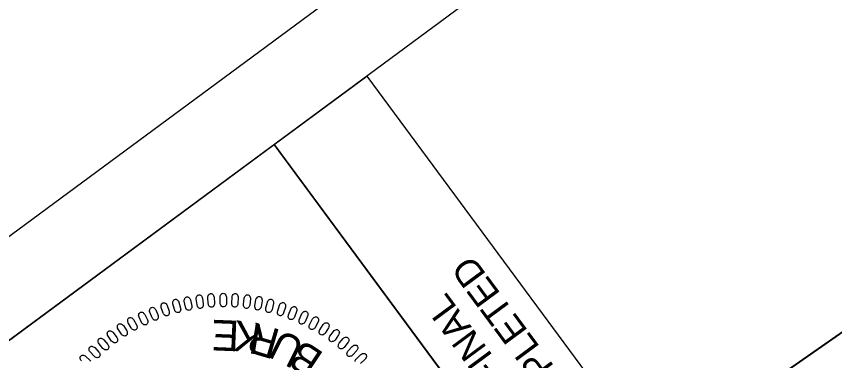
# Model space of a CAD drawing. Extents: x 474314 to 476195, y 501901 to 503905.
# Drawn here: x 474410.1 to 474577, y 503299.5 to 503369.8 of the extents above; entities that cross this region are included whole.
import ezdxf

# ---------------------------------------------------------------- set-up
doc = ezdxf.new("R2010")
doc.units = 0
for name, color, linetype in [('Matchline', 7, 'Continuous'), ('Sheet Clip Boundary CELL', 7, 'Continuous'), ('Sheet PE Seal Cell', 7, 'Continuous'), ('Sheet Plan CELL', 7, 'Continuous'), ('Sheet Plot Border Outside CELL', 7, 'Continuous'), ('Sheet Sticker Exception Certification CELL', 7, 'Continuous')]:
    doc.layers.add(name, color=color, linetype=linetype)

msp = doc.modelspace()

# ---------------------------------------------------------------- linework, layer by layer
at = {"layer": 'Matchline'}
msp.add_line((475026.19, 503617.59), (474539.84, 503278.31), dxfattribs=at)
at = {"layer": 'Sheet Clip Boundary CELL'}
msp.add_lwpolyline([(474600.43, 503196.68), (474460.82, 503093.56), (475070.85, 502267.56), (475070.85, 502267.56), (475070.85, 502267.56), (475070.85, 502267.56), (475070.85, 502267.56), (475070.85, 502267.56), (475422.16, 502337.99), (475422.16, 502337.99), (476046.45, 502713.99), (475412.07, 503572.99), (475380.25, 503549.49), (475256.12, 503717.56), (475223.58, 503693.53), (475026.19, 503617.59), (474539.96, 503278.51)], close=True, dxfattribs=at)
at = {"layer": 'Sheet PE Seal Cell'}
for points in [[(474446.97, 503310.9), (474446.81, 503312.12), (474446.82, 503312.34), (474446.85, 503312.48), (474446.94, 503312.67), (474447.02, 503312.79), (474447.12, 503312.88), (474447.22, 503312.93), (474447.33, 503312.97), (474447.44, 503312.96), (474447.56, 503312.95), (474447.67, 503312.91), (474447.79, 503312.82), (474447.86, 503312.75), (474447.95, 503312.61), (474448.03, 503312.44), (474448.07, 503312.29), (474448.25, 503311.04), (474448.25, 503310.87), (474448.22, 503310.72), (474448.16, 503310.56), (474448.06, 503310.4), (474447.98, 503310.31), (474447.83, 503310.23), (474447.68, 503310.19), (474447.53, 503310.21), (474447.42, 503310.25), (474447.28, 503310.33), (474447.14, 503310.48), (474447.05, 503310.65), (474447, 503310.77)], [(474449.26, 503311.18), (474449.18, 503312.4), (474449.2, 503312.63), (474449.24, 503312.77), (474449.34, 503312.95), (474449.43, 503313.06), (474449.54, 503313.15), (474449.64, 503313.2), (474449.75, 503313.22), (474449.86, 503313.21), (474449.98, 503313.19), (474450.09, 503313.14), (474450.2, 503313.05), (474450.27, 503312.97), (474450.35, 503312.83), (474450.42, 503312.65), (474450.45, 503312.49), (474450.55, 503311.24), (474450.54, 503311.07), (474450.5, 503310.93), (474450.42, 503310.76), (474450.32, 503310.61), (474450.23, 503310.53), (474450.08, 503310.46), (474449.93, 503310.43), (474449.78, 503310.46), (474449.67, 503310.5), (474449.54, 503310.59), (474449.41, 503310.75), (474449.33, 503310.92), (474449.29, 503311.05)], [(474451.69, 503311.28), (474451.68, 503312.51), (474451.72, 503312.73), (474451.77, 503312.87), (474451.88, 503313.04), (474451.98, 503313.15), (474452.09, 503313.23), (474452.19, 503313.27), (474452.31, 503313.29), (474452.42, 503313.27), (474452.54, 503313.24), (474452.64, 503313.19), (474452.75, 503313.09), (474452.81, 503313.01), (474452.88, 503312.86), (474452.94, 503312.68), (474452.96, 503312.52), (474452.98, 503311.26), (474452.96, 503311.09), (474452.91, 503310.95), (474452.83, 503310.79), (474452.72, 503310.65), (474452.62, 503310.57), (474452.46, 503310.51), (474452.31, 503310.49), (474452.16, 503310.53), (474452.06, 503310.58), (474451.93, 503310.68), (474451.81, 503310.84), (474451.74, 503311.02), (474451.71, 503311.15)], [(474454.04, 503311.27), (474454.11, 503312.49), (474454.16, 503312.71), (474454.22, 503312.85), (474454.34, 503313.01), (474454.44, 503313.12), (474454.56, 503313.19), (474454.67, 503313.22), (474454.78, 503313.24), (474454.89, 503313.21), (474455.01, 503313.17), (474455.11, 503313.11), (474455.21, 503313), (474455.26, 503312.92), (474455.32, 503312.77), (474455.37, 503312.58), (474455.38, 503312.42), (474455.32, 503311.17), (474455.29, 503311), (474455.24, 503310.86), (474455.14, 503310.71), (474455.02, 503310.58), (474454.92, 503310.5), (474454.76, 503310.45), (474454.61, 503310.44), (474454.46, 503310.49), (474454.36, 503310.54), (474454.24, 503310.65), (474454.13, 503310.83), (474454.07, 503311.01), (474454.05, 503311.14)], [(474456.44, 503311.06), (474456.59, 503312.28), (474456.65, 503312.49), (474456.72, 503312.63), (474456.85, 503312.78), (474456.96, 503312.88), (474457.08, 503312.95), (474457.19, 503312.97), (474457.3, 503312.98), (474457.41, 503312.95), (474457.53, 503312.9), (474457.63, 503312.83), (474457.72, 503312.72), (474457.77, 503312.63), (474457.82, 503312.48), (474457.86, 503312.29), (474457.86, 503312.13), (474457.72, 503310.88), (474457.68, 503310.72), (474457.61, 503310.58), (474457.51, 503310.43), (474457.38, 503310.31), (474457.27, 503310.24), (474457.11, 503310.2), (474456.96, 503310.2), (474456.82, 503310.26), (474456.72, 503310.32), (474456.6, 503310.43), (474456.5, 503310.61), (474456.46, 503310.8), (474456.44, 503310.93)], [(474440.06, 503309.24), (474439.67, 503310.41), (474439.64, 503310.63), (474439.64, 503310.77), (474439.7, 503310.97), (474439.75, 503311.11), (474439.84, 503311.22), (474439.92, 503311.29), (474440.02, 503311.34), (474440.13, 503311.36), (474440.26, 503311.37), (474440.38, 503311.34), (474440.51, 503311.28), (474440.59, 503311.23), (474440.7, 503311.11), (474440.81, 503310.95), (474440.88, 503310.81), (474441.29, 503309.62), (474441.32, 503309.45), (474441.32, 503309.31), (474441.29, 503309.13), (474441.23, 503308.96), (474441.16, 503308.85), (474441.03, 503308.74), (474440.89, 503308.68), (474440.74, 503308.67), (474440.62, 503308.68), (474440.47, 503308.74), (474440.3, 503308.86), (474440.18, 503309.01), (474440.12, 503309.12)], [(474442.37, 503309.95), (474442.05, 503311.14), (474442.03, 503311.36), (474442.05, 503311.51), (474442.11, 503311.7), (474442.18, 503311.83), (474442.27, 503311.94), (474442.36, 503312), (474442.46, 503312.05), (474442.58, 503312.06), (474442.7, 503312.06), (474442.82, 503312.03), (474442.94, 503311.96), (474443.02, 503311.9), (474443.12, 503311.77), (474443.23, 503311.61), (474443.29, 503311.46), (474443.62, 503310.25), (474443.64, 503310.08), (474443.63, 503309.93), (474443.59, 503309.76), (474443.51, 503309.59), (474443.44, 503309.49), (474443.3, 503309.39), (474443.17, 503309.34), (474443.01, 503309.34), (474442.9, 503309.36), (474442.75, 503309.42), (474442.59, 503309.56), (474442.48, 503309.71), (474442.42, 503309.83)], [(474444.62, 503310.47), (474444.38, 503311.67), (474444.38, 503311.89), (474444.4, 503312.04), (474444.48, 503312.23), (474444.55, 503312.35), (474444.64, 503312.45), (474444.74, 503312.51), (474444.84, 503312.56), (474444.96, 503312.56), (474445.08, 503312.55), (474445.2, 503312.51), (474445.32, 503312.44), (474445.39, 503312.37), (474445.49, 503312.24), (474445.58, 503312.07), (474445.63, 503311.92), (474445.89, 503310.69), (474445.9, 503310.52), (474445.88, 503310.37), (474445.82, 503310.2), (474445.74, 503310.04), (474445.66, 503309.94), (474445.52, 503309.85), (474445.38, 503309.8), (474445.22, 503309.81), (474445.11, 503309.84), (474444.96, 503309.92), (474444.81, 503310.06), (474444.71, 503310.22), (474444.66, 503310.34)], [(474458.77, 503310.77), (474458.99, 503311.98), (474459.06, 503312.19), (474459.14, 503312.32), (474459.28, 503312.46), (474459.4, 503312.55), (474459.52, 503312.61), (474459.63, 503312.63), (474459.74, 503312.63), (474459.85, 503312.59), (474459.96, 503312.54), (474460.05, 503312.46), (474460.14, 503312.35), (474460.18, 503312.26), (474460.22, 503312.1), (474460.25, 503311.91), (474460.24, 503311.75), (474460.02, 503310.51), (474459.97, 503310.35), (474459.9, 503310.22), (474459.79, 503310.08), (474459.65, 503309.96), (474459.54, 503309.9), (474459.38, 503309.87), (474459.22, 503309.88), (474459.08, 503309.94), (474458.99, 503310.01), (474458.88, 503310.13), (474458.8, 503310.32), (474458.76, 503310.51), (474458.76, 503310.64)], [(474461.02, 503310.29), (474461.32, 503311.48), (474461.41, 503311.68), (474461.49, 503311.8), (474461.64, 503311.94), (474461.76, 503312.03), (474461.89, 503312.08), (474462, 503312.09), (474462.12, 503312.08), (474462.22, 503312.03), (474462.33, 503311.98), (474462.42, 503311.89), (474462.5, 503311.77), (474462.53, 503311.68), (474462.56, 503311.52), (474462.58, 503311.33), (474462.56, 503311.17), (474462.27, 503309.95), (474462.2, 503309.79), (474462.12, 503309.66), (474462, 503309.53), (474461.86, 503309.42), (474461.74, 503309.37), (474461.58, 503309.35), (474461.43, 503309.37), (474461.29, 503309.44), (474461.2, 503309.51), (474461.1, 503309.64), (474461.03, 503309.83), (474461.01, 503310.03), (474461.01, 503310.16)], [(474463.42, 503309.68), (474463.79, 503310.85), (474463.89, 503311.05), (474463.98, 503311.17), (474464.14, 503311.3), (474464.26, 503311.37), (474464.4, 503311.41), (474464.51, 503311.42), (474464.62, 503311.41), (474464.72, 503311.35), (474464.83, 503311.29), (474464.91, 503311.2), (474464.98, 503311.07), (474465.01, 503310.98), (474465.03, 503310.82), (474465.03, 503310.63), (474465.01, 503310.47), (474464.63, 503309.27), (474464.56, 503309.11), (474464.48, 503308.99), (474464.34, 503308.87), (474464.19, 503308.77), (474464.08, 503308.72), (474463.91, 503308.71), (474463.76, 503308.74), (474463.63, 503308.82), (474463.54, 503308.9), (474463.45, 503309.03), (474463.39, 503309.23), (474463.38, 503309.42), (474463.39, 503309.56)], [(474435.68, 503307.32), (474435.15, 503308.42), (474435.09, 503308.64), (474435.07, 503308.79), (474435.1, 503308.99), (474435.14, 503309.13), (474435.21, 503309.25), (474435.29, 503309.33), (474435.38, 503309.4), (474435.49, 503309.43), (474435.61, 503309.45), (474435.73, 503309.44), (474435.87, 503309.4), (474435.96, 503309.35), (474436.08, 503309.25), (474436.21, 503309.11), (474436.3, 503308.98), (474436.85, 503307.85), (474436.91, 503307.68), (474436.93, 503307.54), (474436.91, 503307.36), (474436.87, 503307.18), (474436.82, 503307.07), (474436.7, 503306.95), (474436.58, 503306.86), (474436.43, 503306.83), (474436.31, 503306.83), (474436.15, 503306.87), (474435.97, 503306.97), (474435.83, 503307.1), (474435.75, 503307.21)], [(474437.82, 503308.3), (474437.36, 503309.43), (474437.31, 503309.65), (474437.3, 503309.8), (474437.34, 503310), (474437.39, 503310.14), (474437.47, 503310.25), (474437.55, 503310.33), (474437.65, 503310.39), (474437.76, 503310.41), (474437.88, 503310.43), (474438, 503310.41), (474438.13, 503310.36), (474438.22, 503310.31), (474438.34, 503310.2), (474438.46, 503310.05), (474438.54, 503309.91), (474439.02, 503308.75), (474439.06, 503308.59), (474439.07, 503308.44), (474439.05, 503308.26), (474439, 503308.09), (474438.94, 503307.98), (474438.81, 503307.86), (474438.68, 503307.79), (474438.53, 503307.77), (474438.41, 503307.77), (474438.26, 503307.82), (474438.08, 503307.93), (474437.95, 503308.07), (474437.88, 503308.18)], [(474465.64, 503308.91), (474466.08, 503310.05), (474466.2, 503310.24), (474466.3, 503310.36), (474466.46, 503310.47), (474466.59, 503310.54), (474466.73, 503310.57), (474466.84, 503310.57), (474466.95, 503310.55), (474467.05, 503310.49), (474467.15, 503310.42), (474467.22, 503310.33), (474467.29, 503310.2), (474467.31, 503310.1), (474467.32, 503309.94), (474467.31, 503309.75), (474467.28, 503309.59), (474466.83, 503308.42), (474466.75, 503308.27), (474466.65, 503308.15), (474466.51, 503308.04), (474466.36, 503307.95), (474466.24, 503307.91), (474466.07, 503307.91), (474465.92, 503307.94), (474465.8, 503308.04), (474465.72, 503308.12), (474465.64, 503308.26), (474465.59, 503308.46), (474465.59, 503308.65), (474465.61, 503308.78)], [(474467.85, 503308.03), (474468.36, 503309.15), (474468.49, 503309.33), (474468.6, 503309.43), (474468.77, 503309.54), (474468.9, 503309.6), (474469.04, 503309.63), (474469.15, 503309.62), (474469.26, 503309.59), (474469.35, 503309.52), (474469.45, 503309.45), (474469.52, 503309.35), (474469.57, 503309.21), (474469.59, 503309.12), (474469.59, 503308.95), (474469.57, 503308.76), (474469.52, 503308.61), (474469, 503307.47), (474468.91, 503307.32), (474468.81, 503307.21), (474468.67, 503307.11), (474468.51, 503307.03), (474468.38, 503306.99), (474468.22, 503307.01), (474468.07, 503307.05), (474467.95, 503307.15), (474467.88, 503307.24), (474467.8, 503307.38), (474467.77, 503307.59), (474467.78, 503307.78), (474467.81, 503307.91)], [(474433.52, 503306.22), (474432.93, 503307.29), (474432.85, 503307.5), (474432.83, 503307.65), (474432.84, 503307.85), (474432.87, 503307.99), (474432.93, 503308.12), (474433.01, 503308.2), (474433.09, 503308.27), (474433.2, 503308.31), (474433.32, 503308.34), (474433.44, 503308.34), (474433.58, 503308.31), (474433.67, 503308.27), (474433.8, 503308.17), (474433.94, 503308.04), (474434.04, 503307.91), (474434.66, 503306.82), (474434.72, 503306.66), (474434.75, 503306.52), (474434.75, 503306.33), (474434.72, 503306.16), (474434.68, 503306.04), (474434.57, 503305.91), (474434.45, 503305.82), (474434.3, 503305.78), (474434.18, 503305.78), (474434.02, 503305.8), (474433.84, 503305.89), (474433.69, 503306.01), (474433.6, 503306.11)], [(474469.95, 503306.97), (474470.54, 503308.05), (474470.67, 503308.23), (474470.79, 503308.33), (474470.97, 503308.42), (474471.1, 503308.47), (474471.24, 503308.49), (474471.35, 503308.47), (474471.46, 503308.44), (474471.55, 503308.37), (474471.64, 503308.28), (474471.7, 503308.18), (474471.75, 503308.04), (474471.76, 503307.95), (474471.75, 503307.78), (474471.72, 503307.6), (474471.66, 503307.44), (474471.07, 503306.34), (474470.97, 503306.2), (474470.86, 503306.1), (474470.71, 503306), (474470.54, 503305.93), (474470.42, 503305.9), (474470.25, 503305.93), (474470.11, 503305.98), (474470, 503306.09), (474469.93, 503306.18), (474469.87, 503306.33), (474469.84, 503306.53), (474469.87, 503306.72), (474469.91, 503306.85)], [(474431.54, 503304.96), (474430.88, 503305.99), (474430.79, 503306.2), (474430.76, 503306.34), (474430.76, 503306.55), (474430.78, 503306.69), (474430.83, 503306.82), (474430.9, 503306.91), (474430.98, 503306.99), (474431.09, 503307.03), (474431.21, 503307.07), (474431.33, 503307.08), (474431.47, 503307.05), (474431.56, 503307.02), (474431.7, 503306.93), (474431.85, 503306.81), (474431.95, 503306.69), (474432.64, 503305.63), (474432.71, 503305.48), (474432.75, 503305.34), (474432.76, 503305.16), (474432.74, 503304.98), (474432.71, 503304.86), (474432.61, 503304.72), (474432.49, 503304.62), (474432.34, 503304.58), (474432.23, 503304.56), (474432.07, 503304.58), (474431.88, 503304.65), (474431.72, 503304.77), (474431.63, 503304.86)], [(474472.03, 503305.86), (474472.68, 503306.9), (474472.83, 503307.07), (474472.94, 503307.16), (474473.13, 503307.24), (474473.27, 503307.28), (474473.41, 503307.29), (474473.52, 503307.27), (474473.62, 503307.23), (474473.71, 503307.15), (474473.79, 503307.06), (474473.85, 503306.96), (474473.89, 503306.82), (474473.89, 503306.72), (474473.87, 503306.55), (474473.83, 503306.37), (474473.76, 503306.22), (474473.1, 503305.15), (474472.99, 503305.02), (474472.88, 503304.93), (474472.72, 503304.84), (474472.55, 503304.78), (474472.43, 503304.76), (474472.26, 503304.8), (474472.12, 503304.86), (474472.02, 503304.97), (474471.96, 503305.07), (474471.9, 503305.22), (474471.89, 503305.43), (474471.93, 503305.62), (474471.97, 503305.74)], [(474429.56, 503303.54), (474428.83, 503304.53), (474428.73, 503304.73), (474428.69, 503304.87), (474428.68, 503305.07), (474428.69, 503305.22), (474428.74, 503305.35), (474428.8, 503305.44), (474428.88, 503305.53), (474428.98, 503305.58), (474429.09, 503305.62), (474429.21, 503305.64), (474429.35, 503305.62), (474429.45, 503305.59), (474429.59, 503305.51), (474429.75, 503305.4), (474429.86, 503305.29), (474430.61, 503304.28), (474430.7, 503304.13), (474430.74, 503303.99), (474430.76, 503303.81), (474430.76, 503303.63), (474430.73, 503303.51), (474430.64, 503303.37), (474430.53, 503303.26), (474430.38, 503303.2), (474430.27, 503303.18), (474430.11, 503303.19), (474429.91, 503303.25), (474429.75, 503303.36), (474429.65, 503303.44)], [(474474.08, 503304.53), (474474.79, 503305.52), (474474.95, 503305.68), (474475.08, 503305.76), (474475.27, 503305.84), (474475.41, 503305.87), (474475.55, 503305.87), (474475.65, 503305.84), (474475.76, 503305.79), (474475.84, 503305.71), (474475.92, 503305.62), (474475.97, 503305.51), (474475.99, 503305.36), (474476, 503305.26), (474475.96, 503305.1), (474475.91, 503304.92), (474475.83, 503304.78), (474475.11, 503303.75), (474474.99, 503303.63), (474474.87, 503303.54), (474474.71, 503303.46), (474474.54, 503303.42), (474474.41, 503303.41), (474474.25, 503303.45), (474474.12, 503303.52), (474474.02, 503303.64), (474473.96, 503303.74), (474473.91, 503303.9), (474473.92, 503304.1), (474473.97, 503304.29), (474474.02, 503304.41)], [(474427.77, 503302.04), (474426.99, 503302.97), (474426.87, 503303.17), (474426.82, 503303.31), (474426.8, 503303.51), (474426.8, 503303.66), (474426.84, 503303.79), (474426.89, 503303.89), (474426.97, 503303.97), (474427.06, 503304.03), (474427.18, 503304.08), (474427.29, 503304.11), (474427.44, 503304.1), (474427.54, 503304.07), (474427.68, 503304), (474427.85, 503303.9), (474427.96, 503303.8), (474428.78, 503302.84), (474428.87, 503302.69), (474428.93, 503302.56), (474428.96, 503302.38), (474428.96, 503302.2), (474428.94, 503302.08), (474428.86, 503301.93), (474428.76, 503301.82), (474428.62, 503301.75), (474428.5, 503301.72), (474428.34, 503301.72), (474428.14, 503301.77), (474427.98, 503301.87), (474427.87, 503301.95)], [(474475.98, 503303.08), (474476.76, 503304.03), (474476.92, 503304.18), (474477.05, 503304.25), (474477.25, 503304.31), (474477.39, 503304.34), (474477.53, 503304.33), (474477.64, 503304.29), (474477.74, 503304.24), (474477.81, 503304.15), (474477.88, 503304.05), (474477.93, 503303.94), (474477.94, 503303.8), (474477.94, 503303.7), (474477.9, 503303.54), (474477.83, 503303.36), (474477.75, 503303.22), (474476.96, 503302.25), (474476.84, 503302.13), (474476.71, 503302.05), (474476.54, 503301.98), (474476.37, 503301.94), (474476.24, 503301.94), (474476.08, 503302), (474475.95, 503302.08), (474475.86, 503302.2), (474475.81, 503302.31), (474475.78, 503302.46), (474475.79, 503302.67), (474475.85, 503302.85), (474475.91, 503302.97)], [(474477.77, 503301.56), (474478.61, 503302.46), (474478.78, 503302.6), (474478.92, 503302.67), (474479.11, 503302.71), (474479.26, 503302.73), (474479.4, 503302.71), (474479.5, 503302.67), (474479.6, 503302.61), (474479.66, 503302.52), (474479.73, 503302.41), (474479.77, 503302.3), (474479.78, 503302.15), (474479.77, 503302.05), (474479.71, 503301.9), (474479.64, 503301.73), (474479.54, 503301.59), (474478.7, 503300.67), (474478.57, 503300.56), (474478.44, 503300.49), (474478.26, 503300.43), (474478.09, 503300.4), (474477.96, 503300.41), (474477.8, 503300.47), (474477.68, 503300.56), (474477.6, 503300.69), (474477.56, 503300.8), (474477.53, 503300.96), (474477.56, 503301.16), (474477.63, 503301.34), (474477.7, 503301.46)], [(474426.02, 503300.43), (474425.17, 503301.32), (474425.05, 503301.51), (474424.99, 503301.64), (474424.95, 503301.84), (474424.95, 503301.99), (474424.97, 503302.13), (474425.02, 503302.23), (474425.09, 503302.32), (474425.18, 503302.38), (474425.29, 503302.44), (474425.41, 503302.47), (474425.55, 503302.47), (474425.65, 503302.45), (474425.8, 503302.39), (474425.97, 503302.3), (474426.1, 503302.2), (474426.97, 503301.3), (474427.07, 503301.16), (474427.13, 503301.03), (474427.18, 503300.85), (474427.19, 503300.67), (474427.18, 503300.55), (474427.11, 503300.4), (474427.01, 503300.28), (474426.88, 503300.21), (474426.77, 503300.17), (474426.6, 503300.15), (474426.4, 503300.19), (474426.23, 503300.28), (474426.12, 503300.35)]]:
    msp.add_lwpolyline(points, close=True, dxfattribs=at)
for points in [[(474423.39, 503299.5), (474423.26, 503299.67), (474423.19, 503299.81), (474423.14, 503300.01), (474423.13, 503300.15), (474423.14, 503300.29), (474423.18, 503300.39), (474423.25, 503300.49), (474423.34, 503300.56), (474423.44, 503300.62), (474423.55, 503300.66), (474423.7, 503300.67), (474423.8, 503300.66), (474423.95, 503300.61), (474424.13, 503300.53), (474424.26, 503300.44), (474425.19, 503299.59), (474425.3, 503299.46)], [(474479.2, 503299.36), (474479.24, 503299.56), (474479.32, 503299.73), (474479.39, 503299.84), (474479.48, 503299.94), (474480.37, 503300.79), (474480.55, 503300.91), (474480.69, 503300.97), (474480.89, 503301.01), (474481.03, 503301.01), (474481.17, 503300.99), (474481.27, 503300.94), (474481.36, 503300.87), (474481.43, 503300.78), (474481.49, 503300.67), (474481.52, 503300.55), (474481.52, 503300.41), (474481.5, 503300.31), (474481.44, 503300.16), (474481.35, 503299.99), (474481.25, 503299.86), (474480.34, 503298.99)]]:
    msp.add_lwpolyline(points, dxfattribs=at)
at = {"layer": 'Sheet Plan CELL'}
for points in [[(474341.97, 503254.51), (475233.1, 502047.86), (476077.73, 502671.64), (475186.62, 503878.27)], [(474431.61, 503196.37), (474372.2, 503276.79), (474462.7, 503343.64), (474522.12, 503263.21)]]:
    msp.add_lwpolyline(points, close=True, dxfattribs=at)
at = {"layer": 'Sheet Plot Border Outside CELL'}
msp.add_lwpolyline([(476194.75, 502551.08), (475194.63, 503905.31), (474313.8, 503254.81), (475313.91, 501900.58)], close=True, dxfattribs=at)
at = {"layer": 'Sheet Sticker Exception Certification CELL'}
for p, q in [((474462.7, 503343.64), (474481.6, 503357.6)), ((474462.7, 503343.64), (474481.6, 503357.6)), ((474481.59, 503357.59), (474600.43, 503196.68)), ((474481.59, 503357.59), (474600.43, 503196.68)), ((474581.52, 503182.72), (474462.69, 503343.63)), ((474581.52, 503182.72), (474462.69, 503343.63))]:
    msp.add_line(p, q, dxfattribs=at)

# ---------------------------------------------------------------- texts
at = {"layer": 'Sheet PE Seal Cell'}
for s, rotation, p in [('E', 177.7146, (474455.66, 503307.67)), ('K', 170.8689, (474460.4, 503306.93)), ('R', 163.5939, (474464.24, 503305.75)), ('U', 153.4941, (474469.3, 503303.39)), ('B', 146.3772, (474473.08, 503300.94))]:
    msp.add_text(s, height=6.24, rotation=rotation, dxfattribs=at).set_placement(p)
at = {"layer": 'Sheet Sticker Exception Certification CELL'}
for s, p in [('UNLESS ALL SIGNATURES COMPLETED', (474587.42, 503206.96)), ('UNLESS ALL SIGNATURES COMPLETED', (474587.42, 503206.96)), ('DOCUMENT NOT CONSIDERED FINAL', (474577.33, 503205.82)), ('DOCUMENT NOT CONSIDERED FINAL', (474577.33, 503205.82))]:
    msp.add_text(s, height=5.5, rotation=126.4463, dxfattribs=at).set_placement(p)

doc.saveas('drawing.dxf')
